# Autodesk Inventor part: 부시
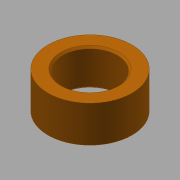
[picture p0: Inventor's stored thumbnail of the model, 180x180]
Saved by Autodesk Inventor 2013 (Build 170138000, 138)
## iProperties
Created: 2015-09
Part Number: 부시
Document SubType Name: Modeling
Designer: mduedu
Density: 1 g/cm^3
Material: 스테인리스강
Author: mduedu
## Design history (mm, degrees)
node "작업 평면1"
node "작업 평면2"
sketch "스케치1"
  geometry: C1 r 7.5 at (0, 0); C2 r 11.5 at (0, 0); 1 further point
  constraints: 2 centre point, 2 coincident
  dimensions: "d0" = 15 diameter of C1; "d1" = 23 diameter of C2
extrude "돌출1" new body sketch "스케치1" stored distance "d2" = 9.85; taper "d3" = 0 deg
chamfer "모따기1" distance "d4" = 0.5; stored, may be unused: second distance "d5" = 2, angle "d6" = 45 deg
node "솔리드1"
